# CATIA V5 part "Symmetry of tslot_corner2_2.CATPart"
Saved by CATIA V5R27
Part number: Symmetry of tslot_corner2_2
Bounding box of the stored display mesh (mm): x -19.05 to 19.05, y -19.05 to 19.05, z -1374.764 to -1219.2
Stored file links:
  \\triton.meca.polymtl.ca\usagers\zaoue\profiles\Desktop\varm_ass\structure prismatique\Symmetry of tslot_corner2_2.CATPart
  \\triton.meca.polymtl.ca\usagers\zaoue\profiles\Desktop\varm_ass\structure prismatique\tslot_corner2.CATPart
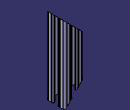
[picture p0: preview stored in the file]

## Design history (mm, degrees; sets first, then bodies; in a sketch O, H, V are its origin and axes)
Body1 (main body)
Body2 "Boss-Extrude1"
  Solid1: linked copy from another document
